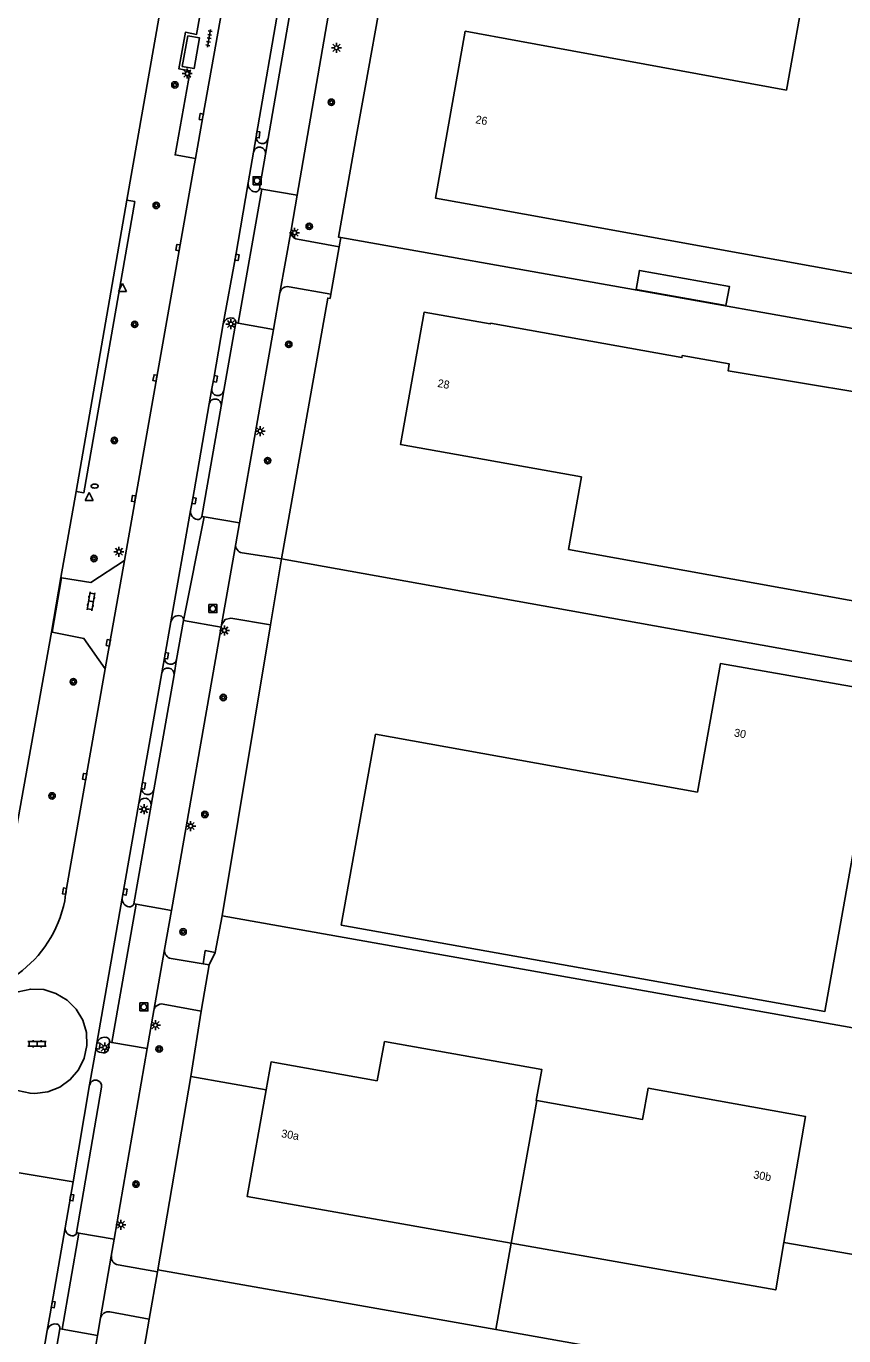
# Model space of a CAD drawing. Extents: x 130998 to 133001, y 398999 to 403002.
# Drawn here: x 132645.5 to 132747.8, y 399161.2 to 399324.9 of the extents above; entities that cross this region are included whole.
import ezdxf

# ---------------------------------------------------------------- set-up
doc = ezdxf.new("R2010")
doc.units = 0
for name, color, linetype in [('gg-afsc-hekwerk', 7, 'Continuous'), ('gg-anno-huisnummerreeks BGT', 7, 'Continuous'), ('gg-bbg-abri', 7, 'Continuous'), ('gg-bbg-hoofdgebouw', 7, 'Continuous'), ('gg-bbg-luifel en loopbrug', 7, 'Continuous'), ('gg-bbg-tussenscheiding', 7, 'Continuous'), ('gg-knt-verharding', 7, 'Continuous'), ('gg-knt-verharding nz', 7, 'Continuous'), ('gt-grn-groengrens', 7, 'Continuous'), ('gt-grn-vlakafsluiter', 7, 'Continuous'), ('gt-grn-weggrens', 7, 'Continuous'), ('gt-symb-boom', 7, 'Continuous'), ('gt-symb-brandkraan', 7, 'Continuous'), ('gt-symb-klinker verharding', 7, 'Continuous'), ('gt-symb-kolk', 7, 'Continuous'), ('gt-symb-lichtmast', 7, 'Continuous'), ('gt-symb-rioolschacht', 7, 'Continuous'), ('gt-symb-tegel verharding', 7, 'Continuous'), ('gt-symb-waterafsluiter', 7, 'Continuous')]:
    doc.layers.add(name, color=color, linetype=linetype)

# ---------------------------------------------------------------- blocks, each defined once
blk = doc.blocks.new('gt0-KOLK')
at = {"layer": 'gt-symb-kolk'}
blk.add_lwpolyline([(0, 0), (0.37, 0), (0.37, 0.4), (-0.38, 0.4), (-0.38, 0), (0, 0)], dxfattribs=at)
blk = doc.blocks.new('gt0-BOOM')
at = {"layer": 'gt-symb-boom'}
for radius in [0.4, 0.2]:
    blk.add_circle((0, 0), radius, dxfattribs=at)
blk = doc.blocks.new('gt0-LMAST')
at = {"layer": 'gt-symb-lichtmast'}
for p, q in [((-0.18, 0.17), (-0.45, 0.44)), ((-0.01, 0.25), (-0.01, 0.62)), ((0.17, 0.17), (0.44, 0.44)), ((-0.26, 0), (-0.63, 0)), ((-0.18, -0.18), (-0.45, -0.45)), ((-0.01, -0.25), (-0.01, -0.63)), ((0.44, -0.45), (0.17, -0.18)), ((0.24, 0), (0.62, 0))]:
    blk.add_line(p, q, dxfattribs=at)
blk.add_circle((-0.01, 0), 0.25, dxfattribs=at)
blk = doc.blocks.new('gt0-RS')
at = {"layer": 'gt-symb-rioolschacht'}
blk.add_lwpolyline([(-0.5, -0.5), (0.5, -0.5), (0.5, 0.5), (-0.5, 0.5)], close=True, dxfattribs=at)
blk.add_circle((0, 0), 0.375, dxfattribs=at)
blk = doc.blocks.new('gt0-TEG1')
at = {"layer": 'gt-symb-tegel verharding'}
for p, q in [((-1.12, 0), (1.12, 0)), ((-0.9, -0.25), (-0.9, 0.25)), ((-0.45, -0.25), (-0.45, 0.25)), ((0, -0.25), (0, 0.25)), ((0.45, -0.25), (0.45, 0.25)), ((0.9, -0.25), (0.9, 0.25))]:
    blk.add_line(p, q, dxfattribs=at)
blk = doc.blocks.new('gt0-WAFSL')
at = {"layer": 'gt-symb-waterafsluiter'}
for p, q in [((-0.5, -0.33), (0, 0.67)), ((0, 0.67), (0.5, -0.33)), ((0.5, -0.33), (-0.5, -0.33))]:
    blk.add_line(p, q, dxfattribs=at)
blk = doc.blocks.new('gt0-KL1')
at = {"layer": 'gt-symb-klinker verharding'}
for p, q in [((-1.15, 0.3), (1.15, 0.3)), ((-1, -0.3), (-1, 0.3)), ((-0.5, 0.3), (-0.5, 0.45)), ((0, -0.3), (0, 0.3)), ((0.5, 0.3), (0.5, 0.45)), ((1, -0.3), (1, 0.3)), ((-1.15, -0.3), (1.15, -0.3)), ((-0.5, -0.45), (-0.5, -0.3)), ((0.5, -0.45), (0.5, -0.3))]:
    blk.add_line(p, q, dxfattribs=at)
blk = doc.blocks.new('gt0-BR')
at = {"layer": 'gt-symb-brandkraan'}
for centre, radius, start, end in [((-0.24, 0), 0.206, 107.5669, 252.4331), ((0.6, -2.66), 3, 106.892, 107.5669), ((0, -0.69), 0.938, 73.108, 106.892), ((-0.6, -2.66), 3, 72.4331, 73.108), ((0.24, 0), 0.206, 287.567, 72.4331), ((0.6, 2.66), 3, 252.4331, 253.108), ((0, 0.69), 0.938, 253.108, 286.8921), ((-0.6, 2.66), 3, 286.8921, 287.567)]:
    blk.add_arc(centre, radius, start, end, dxfattribs=at)

msp = doc.modelspace()

# ---------------------------------------------------------------- linework, layer by layer
at = {"layer": 'gg-afsc-hekwerk'}
for p, q in [((132690.12, 399329.51), (132687.92, 399317.24)), ((132687.92, 399317.24), (132686.85, 399311.3)), ((132651.76, 399266.77), (132658.12, 399303.15)), ((132684.66, 399297.34), (132684.87, 399298.5)), ((132684.87, 399298.5), (132771.21, 399283.14)), ((132683.61, 399291.42), (132684.66, 399297.34)), ((132683.61, 399291.42), (132683.52, 399290.88)), ((132649.87, 399256), (132651.76, 399266.77)), ((132676.07, 399250.09), (132677.44, 399258.32)), ((132677.44, 399258.32), (132762.93, 399243.01)), ((132648.68, 399249.19), (132649.87, 399256)), ((132644.3, 399224.71), (132648.68, 399249.19)), ((132670.04, 399213.74), (132676.07, 399250.09)), ((132666.12, 399193.66), (132661.99, 399169.47)), ((132675.53, 399192), (132666.12, 399193.66)), ((132706.17, 399172.81), (132704.27, 399162.01)), ((132749.7, 399171.27), (132740.28, 399172.89)), ((132661.95, 399169.25), (132660.92, 399163.3)), ((132661.95, 399169.25), (132661.99, 399169.47)), ((132661.99, 399169.47), (132704.27, 399162.01)), ((132660.92, 399163.3), (132658.07, 399146.96)), ((132704.27, 399162.01), (132746.98, 399154.48))]:
    msp.add_line(p, q, dxfattribs=at)
for points in [[(132658.12, 399303.15), (132662.23, 399326.63), (132665.4, 399343.43)], [(132686.85, 399311.3), (132684.57, 399298.55), (132684.87, 399298.5)], [(132677.44, 399258.32), (132683.24, 399290.93), (132683.52, 399290.88)]]:
    msp.add_lwpolyline(points, dxfattribs=at)
at = {"layer": 'gg-bbg-abri'}
msp.add_lwpolyline([(132665.72, 399323.71), (132667.2, 399323.43), (132666.52, 399319.61), (132665.04, 399319.87), (132665.72, 399323.71)], dxfattribs=at)
at = {"layer": 'gg-bbg-hoofdgebouw'}
for points in [[(132707.2, 399323.04), (132740.6, 399316.93), (132745.54, 399344.46), (132770.39, 399340), (132761.75, 399291.66), (132703.47, 399302.19)], [(132707.2, 399323.04), (132700.44, 399324.28), (132696.7, 399303.42), (132703.47, 399302.19)], [(132713.33, 399259.52), (132714.96, 399268.57), (132692.35, 399272.61), (132695.29, 399289.16), (132703.57, 399287.69), (132703.58, 399287.8)], [(132727.58, 399283.75), (132727.53, 399283.5), (132703.58, 399287.8)], [(132727.58, 399283.75), (132733.44, 399282.7), (132733.3, 399281.84), (132758.96, 399277.57)], [(132713.33, 399259.52), (132754.46, 399252.08), (132758.96, 399277.57)], [(132684.93, 399212.55), (132689.22, 399236.41), (132729.46, 399229.2), (132732.35, 399245.25), (132752.52, 399241.72), (132745.41, 399201.78), (132684.93, 399212.55)], [(132675.53, 399192), (132676.14, 399195.47), (132689.41, 399193.11), (132690.34, 399198.01), (132709.99, 399194.54), (132709.3, 399190.65), (132709.37, 399190.63)], [(132675.53, 399192), (132673.17, 399178.64), (132706.17, 399172.81)], [(132709.37, 399190.63), (132722.61, 399188.29), (132723.3, 399192.18), (132742.98, 399188.66), (132740.28, 399172.89)], [(132706.17, 399172.81), (132739.26, 399166.97), (132740.28, 399172.89)]]:
    msp.add_lwpolyline(points, dxfattribs=at)
at = {"layer": 'gg-bbg-luifel en loopbrug'}
msp.add_lwpolyline([(132721.79, 399291.98), (132722.21, 399294.38), (132733.46, 399292.38), (132733.04, 399289.98), (132721.79, 399291.98)], dxfattribs=at)
at = {"layer": 'gg-bbg-tussenscheiding'}
msp.add_line((132709.37, 399190.63), (132706.17, 399172.81), dxfattribs=at)
at = {"layer": 'gg-knt-verharding'}
for p, q in [((132675.79, 399310.86), (132678.8, 399328.14)), ((132679.41, 399303.78), (132683.51, 399327.37)), ((132675.44, 399308.91), (132675.79, 399310.86)), ((132673.28, 399305.31), (132673.95, 399309.16)), ((132666.53, 399307.49), (132666.68, 399308.35)), ((132674.7, 399304.6), (132675.44, 399308.91)), ((132666.53, 399307.49), (132657.8, 399258.15)), ((132672.02, 399287.81), (132674.98, 399304.55)), ((132674.98, 399304.55), (132674.7, 399304.6)), ((132678.65, 399299.43), (132679.41, 399303.78)), ((132677.26, 399291.59), (132678.65, 399299.43)), ((132679.44, 399298.28), (132684.66, 399297.34)), ((132676.46, 399287.02), (132677.26, 399291.59)), ((132678.4, 399292.35), (132683.61, 399291.42)), ((132670.24, 399279.36), (132671.73, 399287.86)), ((132671.73, 399287.86), (132672.02, 399287.81)), ((132672.18, 399262.82), (132676.46, 399287.02)), ((132669.91, 399277.43), (132670.24, 399279.36)), ((132667.49, 399263.65), (132669.91, 399277.43)), ((132665.21, 399250.65), (132667.77, 399263.6)), ((132667.77, 399263.6), (132667.49, 399263.65)), ((132671.73, 399260.23), (132672.18, 399262.82)), ((132669.97, 399250.1), (132671.73, 399260.23)), ((132677.44, 399258.32), (132672.53, 399259.08)), ((132649.96, 399255.98), (132648.78, 399249.18)), ((132662.83, 399245.98), (132663.62, 399250.45)), ((132664.34, 399245.74), (132665.21, 399250.65)), ((132663.69, 399214.41), (132669.92, 399249.82)), ((132669.92, 399249.82), (132669.97, 399250.1)), ((132664.01, 399243.84), (132664.34, 399245.74)), ((132650.46, 399216.42), (132655.4, 399244.58)), ((132659.95, 399229.74), (132662.5, 399244.1)), ((132661.48, 399229.48), (132664.01, 399243.84)), ((132661.14, 399227.54), (132661.48, 399229.48)), ((132657.54, 399215.95), (132659.62, 399227.81)), ((132658.97, 399215.24), (132661.14, 399227.54)), ((132650.34, 399215.61), (132650.46, 399216.42)), ((132657.06, 399202.65), (132659.26, 399215.19)), ((132659.26, 399215.19), (132658.97, 399215.24)), ((132662.83, 399209.52), (132663.69, 399214.41)), ((132669.15, 399209.16), (132670.04, 399213.74)), ((132670.04, 399213.74), (132754.47, 399198.73)), ((132661.48, 399201.88), (132662.83, 399209.52)), ((132667.67, 399207.71), (132663.65, 399208.4)), ((132668.41, 399207.61), (132667.67, 399207.71)), ((132667.4, 399201.83), (132668.41, 399207.61)), ((132656.23, 399197.91), (132657.06, 399202.65)), ((132660.66, 399197.14), (132661.48, 399201.88)), ((132662.64, 399202.69), (132667.4, 399201.83)), ((132666.12, 399193.66), (132667.4, 399201.83)), ((132655.77, 399196.99), (132655.94, 399197.96)), ((132655.94, 399197.96), (132656.23, 399197.91)), ((132653.46, 399192.59), (132654.27, 399197.24)), ((132654.27, 399197.24), (132654.37, 399197.81)), ((132654.68, 399196.69), (132655.17, 399196.61)), ((132656.54, 399173.32), (132660.66, 399197.14)), ((132651.38, 399180.5), (132653.46, 399192.59)), ((132651.83, 399174.14), (132654.95, 399192.33)), ((132650.38, 399174.75), (132651.38, 399180.5)), ((132650.02, 399162.06), (132652.12, 399174.08)), ((132652.12, 399174.08), (132651.83, 399174.14)), ((132656.17, 399171.21), (132656.54, 399173.32)), ((132654.83, 399163.48), (132656.17, 399171.21)), ((132661.95, 399169.25), (132657.01, 399170.09)), ((132660.92, 399163.3), (132655.97, 399164.22)), ((132646.86, 399154.42), (132648.16, 399161.92)), ((132648.27, 399153.72), (132649.74, 399162.12)), ((132649.74, 399162.12), (132650.02, 399162.06)), ((132654.45, 399161.29), (132654.83, 399163.48)), ((132652.99, 399152.9), (132654.45, 399161.29))]:
    msp.add_line(p, q, dxfattribs=at)
for points in [[(132669.16, 399332.52), (132669.05, 399331.85), (132668.27, 399332.01), (132666.83, 399323.87), (132665.43, 399324.14), (132664.62, 399319.57), (132666.01, 399319.32), (132664.15, 399308.82), (132666.68, 399308.35)], [(132666.68, 399308.35), (132667.62, 399313.56), (132670.85, 399331.72)], [(132674.29, 399311.06), (132674.32, 399311.36), (132677.22, 399327.93)], [(132668.74, 399279.61), (132668.99, 399280.87), (132670.17, 399287.69)], [(132666.08, 399264.38), (132666.31, 399265.63), (132668.42, 399277.72)], [(132657.8, 399258.15), (132653.6, 399255.4), (132649.96, 399255.98)], [(132669.97, 399250.1), (132670.39, 399250.75), (132671.13, 399250.92), (132676.07, 399250.09)], [(132648.78, 399249.18), (132652.74, 399248.4), (132655.4, 399244.58)], [(132667.67, 399207.71), (132667.92, 399209.38), (132669.15, 399209.16)], [(132644.52, 399204.24), (132646.1, 399204.57), (132647.71, 399204.5), (132649.25, 399204.03), (132650.64, 399203.2), (132651.77, 399202.06), (132652.6, 399200.67), (132653.06, 399199.13), (132653.12, 399197.52), (132652.79, 399195.94), (132652.08, 399194.49), (132651.04, 399193.26), (132649.73, 399192.32), (132648.23, 399191.73), (132646.62, 399191.53), (132646.02, 399191.55), (132644.45, 399191.89)]]:
    msp.add_lwpolyline(points, dxfattribs=at)
for centre, radius, start, end in [((132675.04, 399311), 0.76, 175.1447, 349.4167), ((132674.7, 399309.03), 0.757, 350.7818, 169.8206), ((132674.28, 399305.2), 1, 173.8865, 260.6017), ((132674.19, 399304.73), 0.529, 262.2453, 345.4963), ((132679.65, 399299.27), 1.02, 170.9154, 258.1184), ((132678.22, 399291.38), 0.983, 79.793, 167.8895), ((132671.12, 399287.46), 0.978, 79.8946, 166.2751), ((132671.26, 399287.95), 0.474, 349.8136, 85.6509), ((132669.16, 399277.56), 0.758, 350.1054, 167.5268), ((132669.49, 399279.5), 0.762, 171.7767, 349.175), ((132667.09, 399264.24), 1.01, 172.3886, 260.2111), ((132667, 399263.73), 0.5, 260.2222, 349.6418), ((132672.71, 399260.06), 0.996, 170.5797, 259.5121), ((132664.6, 399250.25), 1, 79.4077, 168.6056), ((132664.69, 399250.72), 0.518, 351.7021, 80.2944), ((132663.59, 399245.92), 0.768, 175.2951, 346.6663), ((132663.25, 399243.94), 0.768, 352.6687, 167.5229), ((132660.73, 399229.65), 0.777, 173.981, 347.0093), ((132660.38, 399227.65), 0.772, 351.9486, 168.1989), ((132658.57, 399215.86), 1.04, 174.8395, 258.8011), ((132635.87, 399218.45), 14.75, 262.8159, 348.8953), ((132658.46, 399215.35), 0.517, 259.9285, 347.8059), ((132663.82, 399209.38), 1, 172.1097, 260.2654), ((132662.47, 399201.7), 1.01, 80.6535, 169.5435), ((132655.33, 399197.56), 0.995, 80.1478, 165.2971), ((132655.45, 399198.05), 0.495, 350.0585, 84.376), ((132654.77, 399197.19), 0.508, 174.0228, 259.7502), ((132655.27, 399197.11), 0.513, 258.2853, 346.8777), ((132654.21, 399192.45), 0.756, 350.1708, 169.4839), ((132651.43, 399174.76), 1.05, 180.4451, 259.6913), ((132651.31, 399174.26), 0.542, 263.7394, 347.04), ((132657.19, 399171.1), 1.02, 173.3916, 260.2993), ((132655.81, 399163.22), 1.02, 80.8214, 165.3738), ((132649.14, 399161.72), 1, 79.415, 167.9652), ((132649.27, 399162.22), 0.481, 348.2709, 83.2735)]:
    msp.add_arc(centre, radius, start, end, dxfattribs=at)
at = {"layer": 'gg-knt-verharding nz'}
for p, q in [((132673.95, 399309.16), (132674.29, 399311.06)), ((132668.42, 399277.72), (132668.74, 399279.61)), ((132663.62, 399250.45), (132666.08, 399264.38)), ((132655.4, 399244.58), (132657.8, 399258.15)), ((132662.5, 399244.1), (132662.83, 399245.98)), ((132659.62, 399227.81), (132659.95, 399229.74)), ((132654.37, 399197.81), (132657.54, 399215.95))]:
    msp.add_line(p, q, dxfattribs=at)
for points in [[(132670.17, 399287.69), (132671.69, 399296.04), (132673.28, 399305.31)], [(132648.16, 399161.92), (132648.71, 399165.17), (132650.38, 399174.75)]]:
    msp.add_lwpolyline(points, dxfattribs=at)
at = {"layer": 'gt-grn-groengrens'}
for p, q in [((132649.87, 399256), (132649.96, 399255.98)), ((132648.68, 399249.19), (132648.78, 399249.18))]:
    msp.add_line(p, q, dxfattribs=at)
msp.add_lwpolyline([(132651.76, 399266.77), (132652.74, 399266.59), (132659.11, 399302.98), (132658.12, 399303.15)], dxfattribs=at)
at = {"layer": 'gt-grn-vlakafsluiter'}
msp.add_line((132668.41, 399207.61), (132669.15, 399209.16), dxfattribs=at)
at = {"layer": 'gt-grn-weggrens'}
for p, q in [((132674.98, 399304.55), (132679.41, 399303.78)), ((132672.02, 399287.81), (132676.46, 399287.02)), ((132667.77, 399263.6), (132672.18, 399262.82)), ((132665.21, 399250.65), (132669.92, 399249.82)), ((132659.26, 399215.19), (132663.69, 399214.41)), ((132656.23, 399197.91), (132660.66, 399197.14)), ((132644.64, 399181.62), (132651.38, 399180.5)), ((132652.12, 399174.08), (132656.54, 399173.32)), ((132650.02, 399162.06), (132654.45, 399161.29))]:
    msp.add_line(p, q, dxfattribs=at)

# ---------------------------------------------------------------- block references
at = {"layer": 'gt-symb-boom'}
for p in [(132664.12, 399317.57), (132683.69, 399315.4), (132661.79, 399302.51), (132680.92, 399299.89), (132659.09, 399287.64), (132678.36, 399285.14), (132656.55, 399273.14), (132675.72, 399270.61), (132654, 399258.38), (132651.42, 399242.98), (132670.17, 399241.01), (132648.76, 399228.71), (132667.87, 399226.4), (132665.15, 399211.73), (132662.15, 399197.08), (132659.25, 399180.2)]:
    msp.add_blockref('gt0-BOOM', p, dxfattribs=at)
at = {"layer": 'gt-symb-brandkraan'}
msp.add_blockref('gt0-BR', (132654.08, 399267.43), dxfattribs=at)
at = {"layer": 'gt-symb-klinker verharding', "rotation": -99.9050792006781}
msp.add_blockref('gt0-KL1', (132653.63, 399253.03), dxfattribs=at)
at = {"layer": 'gt-symb-klinker verharding'}
msp.add_blockref('gt0-KL1', (132646.88, 399197.74), dxfattribs=at)
at = {"layer": 'gt-symb-kolk'}
for p, rotation in [((132667.62, 399313.56), 79.51061019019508), ((132674.32, 399311.36), -96.81072449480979), ((132664.71, 399297.2), 79.92566726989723), ((132671.69, 399296.04), -100.29546365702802), ((132661.84, 399280.91), 79.92566727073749), ((132668.99, 399280.87), -101.1991519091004), ((132659.14, 399265.83), 79.10581701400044), ((132666.31, 399265.63), -100.27958378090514), ((132655.99, 399247.82), 79.74640198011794), ((132662.88, 399246.26), -100.25432428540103), ((132653.04, 399231.09), 80.09492079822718), ((132660, 399230), -99.97572577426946), ((132650.52, 399216.79), 81.31914941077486), ((132657.68, 399216.74), -100.08324653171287), ((132654.31, 399197.5), -99.78734282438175), ((132651.04, 399178.54), -99.82847530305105), ((132648.71, 399165.17), -99.56713306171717)]:
    msp.add_blockref('gt0-KOLK', p, dxfattribs=dict(at, rotation=rotation))
at = {"layer": 'gt-symb-lichtmast'}
for p in [(132684.34, 399322.2), (132665.67, 399318.98), (132679.1, 399299.1), (132671.13, 399287.68), (132674.79, 399274.3), (132657.13, 399259.23), (132670.32, 399249.39), (132660.27, 399227.05), (132666.1, 399224.95), (132661.7, 399200.06), (132655.36, 399197.28), (132657.38, 399175.13)]:
    msp.add_blockref('gt0-LMAST', p, dxfattribs=at)
at = {"layer": 'gt-symb-rioolschacht'}
for p in [(132674.4, 399305.59), (132668.87, 399252.12), (132660.24, 399202.34)]:
    msp.add_blockref('gt0-RS', p, dxfattribs=at)
at = {"layer": 'gt-symb-tegel verharding', "rotation": 80.09492079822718}
msp.add_blockref('gt0-TEG1', (132668.39, 399323.4), dxfattribs=at)
at = {"layer": 'gt-symb-waterafsluiter'}
for p in [(132657.58, 399292.08), (132653.38, 399265.98)]:
    msp.add_blockref('gt0-WAFSL', p, dxfattribs=at)

# ---------------------------------------------------------------- texts
at = {"layer": 'gg-anno-huisnummerreeks BGT'}
for s, rotation, p in [('26', 349.9, (132701.65, 399312.79)), ('28', 349.9, (132696.91, 399279.83)), ('30', 349.8, (132733.99, 399236.16)), ('30a', 350.1, (132677.36, 399186.07)), ('30b', 350.3, (132736.41, 399180.93))]:
    msp.add_text(s, height=1, rotation=rotation, dxfattribs=at).set_placement(p)

doc.saveas('drawing.dxf')
